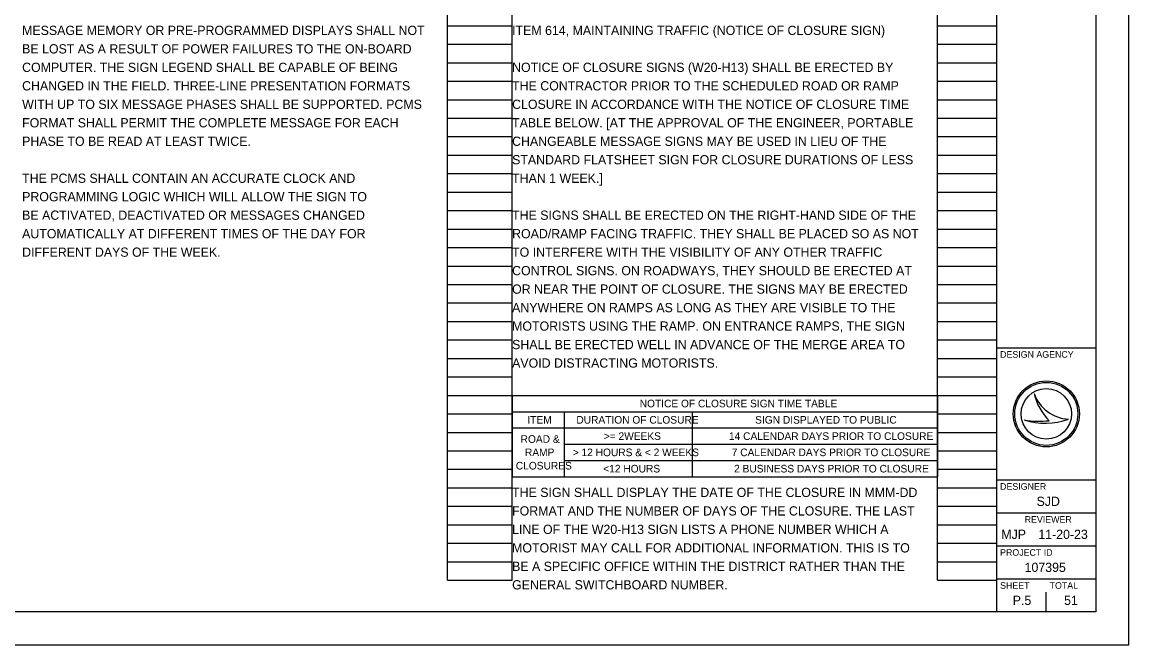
# Model space of a CAD drawing. Extents: x 0 to 34, y 0 to 22.
# Drawn here: x 17.24 to 34, y 0 to 9.43 of the extents above; entities that cross this region are included whole.
import ezdxf

# ---------------------------------------------------------------- set-up
doc = ezdxf.new("R2010")
doc.units = 0
for name, color, linetype in [('SH_Border', 7, 'Continuous'), ('SH_Cut_Line', 7, 'Continuous'), ('SH_Data', 7, 'Continuous'), ('SH_Text', 7, 'Continuous')]:
    doc.layers.add(name, color=color, linetype=linetype)

msp = doc.modelspace()

# ---------------------------------------------------------------- linework, layer by layer
at = {"layer": 'SH_Border'}
for p, q in [((32, 0.5), (32, 21.5)), ((32, 4.5), (33.5, 4.5)), ((32, 2.5), (33.5, 2.5)), ((32, 2), (33.5, 2)), ((32, 1.5), (33.5, 1.5)), ((32, 1), (33.5, 1))]:
    msp.add_line(p, q, dxfattribs=at)
msp.add_lwpolyline([(1.5, 21.5), (33.5, 21.5), (33.5, 0.5), (1.5, 0.5)], close=True, dxfattribs=at)
at = {"layer": 'SH_Cut_Line'}
msp.add_lwpolyline([(0, 0), (34, 0), (34, 22), (0, 22)], close=True, dxfattribs=at)
at = {"layer": 'SH_Data'}
for p, q in [((23.68, 0.98), (23.68, 21.14)), ((24.66, 0.98), (24.66, 21.14)), ((31.1, 0.98), (31.1, 21.14)), ((32, 0.98), (32, 21.14)), ((23.68, 9.38), (24.66, 9.38)), ((31.1, 9.38), (32, 9.38)), ((23.68, 9.1), (24.66, 9.1)), ((31.1, 9.1), (32, 9.1)), ((23.68, 8.82), (24.66, 8.82)), ((31.1, 8.82), (32, 8.82)), ((23.68, 8.54), (24.66, 8.54)), ((31.1, 8.54), (32, 8.54)), ((23.68, 8.26), (24.66, 8.26)), ((31.1, 8.26), (32, 8.26)), ((23.68, 7.98), (24.66, 7.98)), ((31.1, 7.98), (32, 7.98)), ((23.68, 7.7), (24.66, 7.7)), ((31.1, 7.7), (32, 7.7)), ((23.68, 7.42), (24.66, 7.42)), ((31.1, 7.42), (32, 7.42)), ((23.68, 7.14), (24.66, 7.14)), ((31.1, 7.14), (32, 7.14)), ((23.68, 6.86), (24.66, 6.86)), ((31.1, 6.86), (32, 6.86)), ((23.68, 6.58), (24.66, 6.58)), ((31.1, 6.58), (32, 6.58)), ((23.68, 6.3), (24.66, 6.3)), ((31.1, 6.3), (32, 6.3)), ((23.68, 6.02), (24.66, 6.02)), ((31.1, 6.02), (32, 6.02)), ((23.68, 5.74), (24.66, 5.74)), ((31.1, 5.74), (32, 5.74)), ((23.68, 5.46), (24.66, 5.46)), ((31.1, 5.46), (32, 5.46)), ((23.68, 5.18), (24.66, 5.18)), ((31.1, 5.18), (32, 5.18)), ((23.68, 4.9), (24.66, 4.9)), ((31.1, 4.9), (32, 4.9)), ((23.68, 4.62), (24.66, 4.62)), ((31.1, 4.62), (32, 4.62)), ((23.68, 4.34), (24.66, 4.34)), ((31.1, 4.34), (32, 4.34)), ((23.68, 4.06), (24.66, 4.06)), ((31.1, 4.06), (32, 4.06)), ((23.68, 3.78), (24.66, 3.78)), ((31.1, 3.78), (32, 3.78)), ((32.567, 3.81), (32.567, 3.81)), ((23.68, 3.5), (24.66, 3.5)), ((31.1, 3.5), (32, 3.5)), ((32.417, 3.41), (32.417, 3.41)), ((32.75, 3.5), (32.75, 3.5)), ((33.087, 3.419), (33.087, 3.419)), ((23.68, 3.22), (24.66, 3.22)), ((31.1, 3.22), (32, 3.22)), ((23.68, 2.94), (24.66, 2.94)), ((31.1, 2.94), (32, 2.94)), ((23.68, 2.66), (24.66, 2.66)), ((31.1, 2.66), (32, 2.66)), ((23.68, 2.38), (24.66, 2.38)), ((31.1, 2.38), (32, 2.38)), ((23.68, 2.1), (24.66, 2.1)), ((31.1, 2.1), (32, 2.1)), ((23.68, 1.82), (24.66, 1.82)), ((31.1, 1.82), (32, 1.82)), ((23.68, 1.54), (24.66, 1.54)), ((31.1, 1.54), (32, 1.54)), ((23.68, 1.26), (24.66, 1.26)), ((31.1, 1.26), (32, 1.26)), ((23.68, 0.98), (24.66, 0.98)), ((31.1, 0.98), (32, 0.98)), ((32.375, 0.675), (32.375, 0.675)), ((32.75, 0.5), (32.75, 0.8))]:
    msp.add_line(p, q, dxfattribs=at)
for radius in [0.5, 0.477, 0.477, 0.382]:
    msp.add_circle((32.75, 3.5), radius, dxfattribs=at)
for centre, radius, start, end in [((33.116, 3.998), 0.58, 198.9257, 198.9319), ((33.347, 3.97), 0.796, 191.6379, 191.6421), ((33.116, 3.998), 0.58, 198.9319, 267.1657), ((33.347, 3.97), 0.796, 191.6421, 226.0947), ((32.739, 4.37), 1.013, 251.4576, 290.0832), ((32.648, 4.654), 1.266, 259.4964, 259.4995), ((32.739, 4.37), 1.013, 251.4527, 251.4576), ((32.648, 4.654), 1.266, 259.4995, 276.6672)]:
    msp.add_arc(centre, radius, start, end, dxfattribs=at)
at = {"layer": 'SH_Text'}
for p, q in [((24.66, 3.78), (31.1, 3.78)), ((24.66, 3.78), (24.66, 2.546)), ((31.1, 3.78), (31.1, 2.546)), ((24.66, 3.533), (31.1, 3.533)), ((25.45, 3.533), (25.45, 2.546)), ((27.387, 3.533), (27.387, 2.546)), ((24.66, 3.287), (31.1, 3.287)), ((25.45, 3.04), (31.1, 3.04)), ((25.45, 2.793), (31.1, 2.793)), ((24.66, 2.546), (31.1, 2.546))]:
    msp.add_line(p, q, dxfattribs=at)

# ---------------------------------------------------------------- texts
at = {"layer": 'SH_Data'}
for s, height, p in [('DESIGN AGENCY', 0.1, (32.05, 4.35)), ('DESIGNER', 0.1, (32.05, 2.35)), ('SJD', 0.14, (32.602, 2.105)), ('REVIEWER', 0.1, (32.422, 1.85)), ('MJP', 0.14, (32.068, 1.605)), ('11-20-23', 0.14, (32.629, 1.605)), ('PROJECT ID', 0.1, (32.05, 1.35)), ('107395', 0.14, (32.421, 1.105)), ('SHEET', 0.1, (32.05, 0.85)), ('TOTAL', 0.1, (32.8, 0.85)), ('P.5', 0.14, (32.241, 0.605)), ('51', 0.14, (33.019, 0.605))]:
    msp.add_text(s, height=height, dxfattribs=at).set_placement(p)
at = {"layer": 'SH_Text'}
for s, height, p in [('ITEM 614, MAINTAINING TRAFFIC (NOTICE OF CLOSURE SIGN)', 0.14, (24.66, 9.24)), ('MESSAGE MEMORY OR PRE-PROGRAMMED DISPLAYS SHALL NOT', 0.14, (17.24, 9.24)), ('BE LOST AS A RESULT OF POWER FAILURES TO THE ON-BOARD', 0.14, (17.24, 8.96)), ('COMPUTER. THE SIGN LEGEND SHALL BE CAPABLE OF BEING', 0.14, (17.24, 8.68)), ('NOTICE OF CLOSURE SIGNS (W20-H13) SHALL BE ERECTED BY', 0.14, (24.66, 8.68)), ('CHANGED IN THE FIELD. THREE-LINE PRESENTATION FORMATS', 0.14, (17.24, 8.4)), ('THE CONTRACTOR PRIOR TO THE SCHEDULED ROAD OR RAMP', 0.14, (24.66, 8.4)), ('WITH UP TO SIX MESSAGE PHASES SHALL BE SUPPORTED. PCMS', 0.14, (17.24, 8.12)), ('CLOSURE IN ACCORDANCE WITH THE NOTICE OF CLOSURE TIME', 0.14, (24.66, 8.12)), ('FORMAT SHALL PERMIT THE COMPLETE MESSAGE FOR EACH', 0.14, (17.24, 7.84)), ('TABLE BELOW. [AT THE APPROVAL OF THE ENGINEER, PORTABLE', 0.14, (24.66, 7.84)), ('PHASE TO BE READ AT LEAST TWICE.', 0.14, (17.24, 7.56)), ('CHANGEABLE MESSAGE SIGNS MAY BE USED IN LIEU OF THE', 0.14, (24.66, 7.56)), ('STANDARD FLATSHEET SIGN FOR CLOSURE DURATIONS OF LESS', 0.14, (24.66, 7.28)), ('THE PCMS SHALL CONTAIN AN ACCURATE CLOCK AND', 0.14, (17.24, 7)), ('THAN 1 WEEK.]', 0.14, (24.66, 7)), ('PROGRAMMING LOGIC WHICH WILL ALLOW THE SIGN TO', 0.14, (17.24, 6.72)), ('BE ACTIVATED, DEACTIVATED OR MESSAGES CHANGED', 0.14, (17.24, 6.44)), ('THE SIGNS SHALL BE ERECTED ON THE RIGHT-HAND SIDE OF THE', 0.14, (24.66, 6.44)), ('AUTOMATICALLY AT DIFFERENT TIMES OF THE DAY FOR', 0.14, (17.24, 6.16)), ('ROAD/RAMP FACING TRAFFIC. THEY SHALL BE PLACED SO AS NOT', 0.14, (24.66, 6.16)), ('DIFFERENT DAYS OF THE WEEK.', 0.14, (17.24, 5.88)), ('TO INTERFERE WITH THE VISIBILITY OF ANY OTHER TRAFFIC', 0.14, (24.66, 5.88)), ('CONTROL SIGNS. ON ROADWAYS, THEY SHOULD BE ERECTED AT', 0.14, (24.66, 5.6)), ('OR NEAR THE POINT OF CLOSURE. THE SIGNS MAY BE ERECTED', 0.14, (24.66, 5.32)), ('ANYWHERE ON RAMPS AS LONG AS THEY ARE VISIBLE TO THE', 0.14, (24.66, 5.04)), ('MOTORISTS USING THE RAMP. ON ENTRANCE RAMPS, THE SIGN', 0.14, (24.66, 4.76)), ('SHALL BE ERECTED WELL IN ADVANCE OF THE MERGE AREA TO', 0.14, (24.66, 4.48)), ('AVOID DISTRACTING MOTORISTS.', 0.14, (24.66, 4.2)), ('NOTICE OF CLOSURE SIGN TIME TABLE', 0.11535, (26.592, 3.599)), ('ITEM', 0.1154, (24.891, 3.352)), ('DURATION OF CLOSURE', 0.11535, (25.633, 3.352)), ('SIGN DISPLAYED TO PUBLIC', 0.11535, (28.341, 3.352)), ('>= 2WEEKS', 0.1154, (26.048, 3.105)), ('14 CALENDAR DAYS PRIOR TO CLOSURE', 0.11535, (27.944, 3.105)), ('ROAD & ', 0.1154, (24.789, 3.061)), ('RAMP ', 0.1154, (24.855, 2.859)), ('> 12 HOURS & < 2 WEEKS', 0.11535, (25.578, 2.859)), ('7 CALENDAR DAYS PRIOR TO CLOSURE', 0.11535, (27.986, 2.859)), ('CLOSURES', 0.1154, (24.716, 2.657)), ('<12 HOURS', 0.1154, (26.04, 2.612)), ('2 BUSINESS DAYS PRIOR TO CLOSURE', 0.11535, (28.022, 2.612)), ('THE SIGN SHALL DISPLAY THE DATE OF THE CLOSURE IN MMM-DD', 0.14, (24.66, 2.24)), ('FORMAT AND THE NUMBER OF DAYS OF THE CLOSURE. THE LAST', 0.14, (24.66, 1.96)), ('LINE OF THE W20-H13 SIGN LISTS A PHONE NUMBER WHICH A', 0.14, (24.66, 1.68)), ('MOTORIST MAY CALL FOR ADDITIONAL INFORMATION. THIS IS TO', 0.14, (24.66, 1.4)), ('BE A SPECIFIC OFFICE WITHIN THE DISTRICT RATHER THAN THE', 0.14, (24.66, 1.12)), ('GENERAL SWITCHBOARD NUMBER.', 0.14, (24.66, 0.84))]:
    msp.add_text(s, height=height, dxfattribs=at).set_placement(p)

doc.saveas('drawing.dxf')
